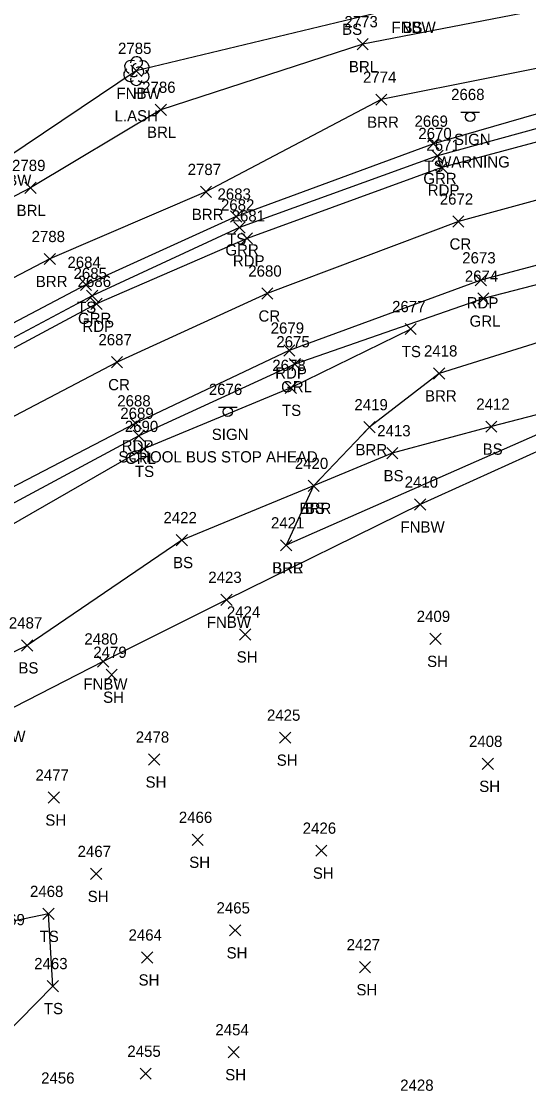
# Model space of a CAD drawing. Extents: x 1443590 to 1445966, y 578314 to 580556.
# Drawn here: x 1444460.3 to 1444550.7, y 578967.8 to 579157.3 of the extents above; entities that cross this region are included whole.
import ezdxf

# ---------------------------------------------------------------- set-up
doc = ezdxf.new("R2010")
doc.units = 0
for name, color, linetype in [('L_A', 7, 'Continuous'), ('L_C', 7, 'Continuous'), ('L_I', 7, 'Continuous'), ('L_TIC', 7, 'Continuous'), ('LABL', 7, 'Continuous'), ('LELB', 7, 'Continuous'), ('LFNC', 7, 'Continuous'), ('LTD', 7, 'Continuous'), ('P_A', 7, 'Continuous'), ('P_I', 7, 'Continuous'), ('P_TIC', 7, 'Continuous'), ('PET', 7, 'Continuous'), ('PRC', 7, 'Continuous'), ('R_A', 7, 'Continuous'), ('R_I', 7, 'Continuous'), ('R_TIC', 7, 'Continuous'), ('RGR', 7, 'Continuous'), ('S_A', 7, 'Continuous'), ('S_C', 7, 'Continuous'), ('S_I', 7, 'Continuous'), ('SSGN', 7, 'Continuous')]:
    doc.layers.add(name, color=color, linetype=linetype)

msp = doc.modelspace()

# ---------------------------------------------------------------- linework, layer by layer
at = {"layer": 'L_TIC'}
for points in [[(1444520.13, 579152.26), (1444522.13, 579154.26)], [(1444522.13, 579152.26), (1444520.13, 579154.26)], [(1444479.82, 579147.51), (1444481.82, 579149.51)], [(1444481.82, 579147.51), (1444479.82, 579149.51)], [(1444523.44, 579142.38), (1444525.44, 579144.38)], [(1444525.44, 579142.38), (1444523.44, 579144.38)], [(1444484.17, 579140.59), (1444486.17, 579142.59)], [(1444486.17, 579140.59), (1444484.17, 579142.59)], [(1444532.71, 579134.55), (1444534.71, 579136.55)], [(1444534.71, 579134.55), (1444532.71, 579136.55)], [(1444460.96, 579126.68), (1444462.96, 579128.68)], [(1444462.96, 579126.68), (1444460.96, 579128.68)], [(1444492.22, 579125.97), (1444494.22, 579127.97)], [(1444494.22, 579125.97), (1444492.22, 579127.97)], [(1444497.58, 579121.6), (1444499.58, 579123.6)], [(1444499.58, 579121.6), (1444497.58, 579123.6)], [(1444464.43, 579114.04), (1444466.43, 579116.04)], [(1444466.43, 579114.04), (1444464.43, 579116.04)], [(1444470.85, 579109.46), (1444472.85, 579111.46)], [(1444472.85, 579109.46), (1444470.85, 579111.46)], [(1444528.67, 579101.58), (1444530.67, 579103.58)], [(1444530.67, 579101.58), (1444528.67, 579103.58)], [(1444533.73, 579093.69), (1444535.73, 579095.69)], [(1444535.73, 579093.69), (1444533.73, 579095.69)], [(1444507.34, 579091.12), (1444509.34, 579093.12)], [(1444509.34, 579091.12), (1444507.34, 579093.12)], [(1444521.35, 579084.12), (1444523.35, 579086.12)], [(1444523.35, 579084.12), (1444521.35, 579086.12)], [(1444543.04, 579084.22), (1444545.04, 579086.22)], [(1444545.04, 579084.22), (1444543.04, 579086.22)], [(1444481.16, 579080.26), (1444483.16, 579082.26)], [(1444483.16, 579080.26), (1444481.16, 579082.26)], [(1444525.4, 579079.49), (1444527.4, 579081.49)], [(1444527.4, 579079.49), (1444525.4, 579081.49)], [(1444511.39, 579073.69), (1444513.39, 579075.69)], [(1444513.39, 579073.69), (1444511.39, 579075.69)], [(1444511.39, 579073.69), (1444513.39, 579075.69)], [(1444513.39, 579073.69), (1444511.39, 579075.69)], [(1444530.38, 579070.36), (1444532.38, 579072.36)], [(1444532.38, 579070.36), (1444530.38, 579072.36)], [(1444487.91, 579064.04), (1444489.91, 579066.04)], [(1444489.91, 579064.04), (1444487.91, 579066.04)], [(1444506.48, 579063.11), (1444508.48, 579065.11)], [(1444508.48, 579063.11), (1444506.48, 579065.11)], [(1444506.48, 579063.11), (1444508.48, 579065.11)], [(1444508.48, 579063.11), (1444506.48, 579065.11)], [(1444495.89, 579053.42), (1444497.89, 579055.42)], [(1444497.89, 579053.42), (1444495.89, 579055.42)], [(1444499.2, 579047.26), (1444501.2, 579049.26)], [(1444501.2, 579047.26), (1444499.2, 579049.26)], [(1444533.1, 579046.47), (1444535.1, 579048.47)], [(1444535.1, 579046.47), (1444533.1, 579048.47)], [(1444460.38, 579045.31), (1444462.38, 579047.31)], [(1444462.38, 579045.31), (1444460.38, 579047.31)], [(1444473.91, 579042.46), (1444475.91, 579044.46)], [(1444475.91, 579042.46), (1444473.91, 579044.46)], [(1444475.43, 579040.09), (1444477.43, 579042.09)], [(1444477.43, 579040.09), (1444475.43, 579042.09)], [(1444506.34, 579028.9), (1444508.34, 579030.9)], [(1444508.34, 579028.9), (1444506.34, 579030.9)], [(1444482.98, 579025), (1444484.98, 579027)], [(1444484.98, 579025), (1444482.98, 579027)], [(1444542.39, 579024.24), (1444544.39, 579026.24)], [(1444544.39, 579024.24), (1444542.39, 579026.24)], [(1444465.12, 579018.24), (1444467.12, 579020.24)], [(1444467.12, 579018.24), (1444465.12, 579020.24)], [(1444490.75, 579010.73), (1444492.75, 579012.73)], [(1444492.75, 579010.73), (1444490.75, 579012.73)], [(1444512.76, 579008.8), (1444514.76, 579010.8)], [(1444514.76, 579008.8), (1444512.76, 579010.8)], [(1444472.67, 579004.66), (1444474.67, 579006.66)], [(1444474.67, 579004.66), (1444472.67, 579006.66)], [(1444464.19, 578997.55), (1444466.19, 578999.55)], [(1444466.19, 578997.55), (1444464.19, 578999.55)], [(1444497.4, 578994.62), (1444499.4, 578996.62)], [(1444499.4, 578994.62), (1444497.4, 578996.62)], [(1444481.74, 578989.8), (1444483.74, 578991.8)], [(1444483.74, 578989.8), (1444481.74, 578991.8)], [(1444520.53, 578988.06), (1444522.53, 578990.06)], [(1444522.53, 578988.06), (1444520.53, 578990.06)], [(1444464.94, 578984.71), (1444466.94, 578986.71)], [(1444466.94, 578984.71), (1444464.94, 578986.71)], [(1444497.16, 578972.95), (1444499.16, 578974.95)], [(1444499.16, 578972.95), (1444497.16, 578974.95)], [(1444481.48, 578969.12), (1444483.48, 578971.12)], [(1444483.48, 578969.12), (1444481.48, 578971.12)]]:
    msp.add_lwpolyline(points, dxfattribs=at)
at = {"layer": 'LABL'}
for points in [[(1444712.54, 579167.85), (1444697.6, 579169.93), (1444652.08, 579178.48), (1444624.95, 579180.17), (1444611.5, 579175.57), (1444588.82, 579169.39), (1444561.97, 579161.22), (1444521.13, 579153.26), (1444485.17, 579141.59), (1444461.96, 579127.68), (1444423.87, 579107.83), (1444406.2, 579097.14), (1444395.91, 579089.33), (1444383.1, 579088.69), (1444377.98, 579081.32), (1444375.45, 579066.09), (1444387.55, 579066.41), (1444398.68, 579076.41), (1444413.49, 579086.33)], [(1444712.54, 579167.85), (1444718.35, 579164.22), (1444718.26, 579161.73), (1444696.4, 579163.57), (1444656.01, 579167.98), (1444612.17, 579160.88), (1444583.77, 579156.18), (1444564.87, 579151.47), (1444524.44, 579143.38), (1444493.22, 579126.97), (1444465.43, 579115.04), (1444435.17, 579099.27), (1444413.49, 579086.33)], [(1444694.2, 579116.07), (1444660.17, 579122.03), (1444619.71, 579118.69), (1444593.21, 579113.2), (1444563.33, 579103.61), (1444534.73, 579094.69), (1444522.35, 579085.12), (1444512.39, 579074.69), (1444507.48, 579064.11)], [(1444694.2, 579116.07), (1444661.24, 579112.36), (1444623.46, 579104.14), (1444596.63, 579097.35), (1444588.29, 579095.31), (1444555.76, 579085.36), (1444507.48, 579064.11)]]:
    msp.add_lwpolyline(points, dxfattribs=at)
at = {"layer": 'LELB'}
for points in [[(1444655.65, 579153.87), (1444655.96, 579156.44), (1444615.16, 579153.66), (1444570.72, 579146.18), (1444533.71, 579135.55), (1444498.58, 579122.6), (1444471.85, 579110.46), (1444439, 579093.18), (1444418.36, 579080.86), (1444402.03, 579073.49), (1444397.21, 579069.21), (1444392.99, 579064.18)], [(1444529.67, 579102.58), (1444508.34, 579092.12), (1444482.16, 579081.26), (1444453.29, 579064.71), (1444433.08, 579054.44), (1444417.17, 579046.55), (1444411.14, 579043.39), (1444405.77, 579042.57)], [(1444566.52, 579091.05), (1444544.04, 579085.22), (1444526.4, 579080.49), (1444512.39, 579074.69), (1444488.91, 579065.04), (1444461.38, 579046.31), (1444441.32, 579036.58), (1444429.07, 579030.89), (1444423.05, 579028.56)], [(1444453.94, 578962.61), (1444453.99, 578973.55), (1444465.94, 578985.71), (1444465.19, 578998.55), (1444446.92, 578994.78), (1444439.55, 579000.55), (1444432.64, 579022.06)]]:
    msp.add_lwpolyline(points, dxfattribs=at)
at = {"layer": 'LFNC'}
for points in [[(1444560.1, 579167.55), (1444546.27, 579164.71), (1444529.77, 579160.23), (1444480.82, 579148.51), (1444457.79, 579133.06), (1444422.53, 579110), (1444405.51, 579098.29), (1444395.54, 579091.93), (1444390.51, 579099.64), (1444385.34, 579099.67), (1444374.49, 579098.14), (1444368.47, 579095.23)], [(1444890.65, 579013.76), (1444887.91, 579035.57), (1444886.02, 579049.24), (1444887.33, 579069.98), (1444887.17, 579070.25), (1444893.55, 579088.91), (1444852.86, 579095.07), (1444811.04, 579100.21), (1444771.7, 579104.54), (1444701.16, 579115.56), (1444661.88, 579109.45), (1444623.2, 579102.04), (1444597.43, 579094.83), (1444589.4, 579093.21), (1444556.52, 579082.74), (1444531.38, 579071.36), (1444496.89, 579054.42), (1444474.91, 579043.46), (1444456.73, 579034.11), (1444432.64, 579022.06), (1444424.59, 579018.08), (1444422.86, 579017.09), (1444428.49, 579008.38), (1444434.19, 578999.12)]]:
    msp.add_lwpolyline(points, dxfattribs=at)
at = {"layer": 'LTD'}
msp.add_line((1444480.82, 579148.51), (1444480.82, 579148.51), dxfattribs=at)
msp.add_line((1444480.82, 579148.51), (1444480.82, 579148.51), dxfattribs=at)
msp.add_arc((1444480.86, 579149.95), 1.05, 335.5272, 180.9563, dxfattribs=at)
for centre, major_axis, ratio, start_param, end_param in [((1444480.02, 579149.18), (1.21, -0.51), 0.895232, 1.570796, 4.712389), ((1444481.86, 579149.1), (-1.14, -0.48), 0.949671, 1.570796, 4.712389), ((1444479.73, 579147.8), (0.58, -1.04), 0.959034, 3.141593, 6.283185), ((1444480.61, 579148.97), (-0.208, -0.792), 0.645439, 3.141593, 6.283185), ((1444481.32, 579148.35), (-0.5, 0.667), 0.989748, 3.141593, 6.283185), ((1444481.82, 579147.68), (-1.09, 0.79), 0.841452, 1.570796, 4.712389), ((1444480.82, 579147.01), (0.26, 1.06), 0.942809, 1.570796, 4.712389), ((1444480.36, 579147.76), (-0.625, -0.083), 0.423636, 0, 3.141593)]:
    msp.add_ellipse(centre, major_axis=major_axis, ratio=ratio, start_param=start_param, end_param=end_param, dxfattribs=at)
at = {"layer": 'P_TIC'}
for points in [[(1444534.21, 579130.29), (1444536.21, 579132.29)], [(1444536.21, 579130.29), (1444534.21, 579132.29)], [(1444537.16, 579120.71), (1444539.16, 579122.71)], [(1444539.16, 579120.71), (1444537.16, 579122.71)], [(1444499.53, 579117.71), (1444501.53, 579119.71)], [(1444501.53, 579117.71), (1444499.53, 579119.71)], [(1444541.16, 579110.25), (1444543.16, 579112.25)], [(1444543.16, 579110.25), (1444541.16, 579112.25)], [(1444503.14, 579107.9), (1444505.14, 579109.9)], [(1444505.14, 579107.9), (1444503.14, 579109.9)], [(1444472.73, 579106.06), (1444474.73, 579108.06)], [(1444474.73, 579106.06), (1444472.73, 579108.06)], [(1444507.06, 579097.76), (1444509.06, 579099.76)], [(1444509.06, 579097.76), (1444507.06, 579099.76)], [(1444476.38, 579095.69), (1444478.38, 579097.69)], [(1444478.38, 579095.69), (1444476.38, 579097.69)], [(1444479.73, 579084.81), (1444481.73, 579086.81)], [(1444481.73, 579084.81), (1444479.73, 579086.81)]]:
    msp.add_lwpolyline(points, dxfattribs=at)
at = {"layer": 'PET'}
for points in [[(1444572.86, 579141.4), (1444535.21, 579131.29), (1444500.53, 579118.71), (1444473.73, 579107.06), (1444441.14, 579089.65), (1444420.58, 579076.86), (1444394.66, 579061.33)], [(1444577.17, 579120.56), (1444542.16, 579111.25), (1444508.06, 579098.76), (1444480.73, 579085.81), (1444450.77, 579070.32), (1444431.1, 579059.46), (1444404.84, 579044.29), (1444399.61, 579053.05), (1444394.66, 579061.33)]]:
    msp.add_lwpolyline(points, dxfattribs=at)
at = {"layer": 'PRC'}
msp.add_lwpolyline([(1444575.01, 579131.71), (1444538.16, 579121.71), (1444504.14, 579108.9), (1444477.38, 579096.69), (1444445.79, 579080.13), (1444425.28, 579068.48), (1444399.61, 579053.05)], dxfattribs=at)
at = {"layer": 'R_TIC'}
for points in [[(1444533.43, 579132.37), (1444535.43, 579134.37)], [(1444535.43, 579132.37), (1444533.43, 579134.37)], [(1444498.2, 579119.66), (1444500.2, 579121.66)], [(1444500.2, 579119.66), (1444498.2, 579121.66)], [(1444471.94, 579107.48), (1444473.94, 579109.48)], [(1444473.94, 579107.48), (1444471.94, 579109.48)], [(1444541.61, 579106.99), (1444543.61, 579108.99)], [(1444543.61, 579106.99), (1444541.61, 579108.99)], [(1444508.05, 579095.32), (1444510.05, 579097.32)], [(1444510.05, 579095.32), (1444508.05, 579097.32)], [(1444480.27, 579082.6), (1444482.27, 579084.6)], [(1444482.27, 579082.6), (1444480.27, 579084.6)]]:
    msp.add_lwpolyline(points, dxfattribs=at)
at = {"layer": 'RGR'}
for points in [[(1444721.53, 579155.32), (1444696.74, 579155.42), (1444655.65, 579153.87), (1444615.28, 579151.28), (1444571.27, 579143.45), (1444534.43, 579133.37), (1444499.2, 579120.66), (1444472.94, 579108.48), (1444439.95, 579090.95), (1444419.6, 579078.42), (1444394.06, 579062.05)], [(1444761.39, 579118.56), (1444730.45, 579124.57), (1444695.1, 579127.47), (1444656.18, 579127.4), (1444619.28, 579124.62), (1444577.8, 579117.06), (1444542.61, 579107.99), (1444509.05, 579096.32), (1444481.27, 579083.6), (1444451.92, 579067.89), (1444431.87, 579057.62), (1444404.79, 579043.92)]]:
    msp.add_lwpolyline(points, dxfattribs=at)
at = {"layer": 'SSGN'}
for p, q in [((1444538.59, 579141.16), (1444541.93, 579141.16)), ((1444540.24, 579140.33), (1444540.24, 579140.33)), ((1444495.47, 579088.71), (1444498.8, 579088.71)), ((1444497.11, 579087.87), (1444497.11, 579087.87))]:
    msp.add_line(p, q, dxfattribs=at)
for centre in [(1444540.24, 579140.33), (1444497.11, 579087.87)]:
    msp.add_circle(centre, 0.833, dxfattribs=at)

# ---------------------------------------------------------------- texts
at = {"layer": 'L_A'}
for s, p in [('BS', (1444517.46, 579154.9)), ('FNBW', (1444526.25, 579155.23)), ('BS', (1444528.21, 579155.23)), ('BRL', (1444518.67, 579148.26)), ('FNBW', (1444477.29, 579143.51)), ('H', (1444480.25, 579143.51)), ('BRR', (1444521.92, 579138.38)), ('BRL', (1444482.72, 579136.59)), ('TS', (1444532.12, 579130.55)), ('FNBW', (1444454.26, 579128.06)), ('BRL', (1444459.5, 579122.68)), ('BRR', (1444490.7, 579121.97)), ('TS', (1444496.98, 579117.6)), ('BRR', (1444462.92, 579110.04)), ('TS', (1444470.26, 579105.46)), ('TS', (1444528.08, 579097.58)), ('BRR', (1444532.22, 579089.69)), ('TS', (1444506.75, 579087.12)), ('BRR', (1444519.84, 579080.12)), ('BS', (1444542.48, 579080.22)), ('TS', (1444480.57, 579076.26)), ('BS', (1444524.84, 579075.49)), ('BRR', (1444509.88, 579069.69)), ('BS', (1444510.83, 579069.69)), ('FNBW', (1444527.85, 579066.36)), ('BS', (1444487.36, 579060.04)), ('BRR', (1444504.97, 579059.11)), ('BRL', (1444505.02, 579059.11)), ('FNBW', (1444493.37, 579049.42)), ('SH', (1444498.68, 579043.26)), ('SH', (1444532.59, 579042.47)), ('BS', (1444459.82, 579041.31)), ('FNBW', (1444471.38, 579038.46)), ('SH', (1444474.91, 579036.09)), ('FNBW', (1444453.21, 579029.11)), ('SH', (1444505.82, 579024.9)), ('SH', (1444482.46, 579021)), ('SH', (1444541.88, 579020.24)), ('SH', (1444464.61, 579014.24)), ('SH', (1444490.24, 579006.73)), ('SH', (1444512.25, 579004.8)), ('SH', (1444472.15, 579000.66)), ('TS', (1444463.6, 578993.55)), ('SH', (1444496.89, 578990.62)), ('SH', (1444481.22, 578985.8)), ('SH', (1444520.01, 578984.06)), ('TS', (1444464.35, 578980.71)), ('SH', (1444496.65, 578968.95))]:
    msp.add_text(s, height=2, dxfattribs=at).set_placement(p)
at = {"layer": 'L_C'}
msp.add_text('L.ASH', height=2, dxfattribs=at).set_placement((1444476.94, 579139.51))
at = {"layer": 'L_I'}
for s, p in [('2773', (1444517.87, 579156.26)), ('2785', (1444477.56, 579151.51)), ('2785', (1444477.56, 579151.51)), ('2774', (1444521.18, 579146.38)), ('2786', (1444481.86, 579144.59)), ('2669', (1444530.35, 579138.55)), ('2789', (1444458.69, 579130.68)), ('2787', (1444489.96, 579129.97)), ('2683', (1444495.27, 579125.6)), ('2788', (1444462.17, 579118.04)), ('2684', (1444468.55, 579113.46)), ('2677', (1444526.36, 579105.58)), ('2418', (1444532.04, 579097.69)), ('2678', (1444505.03, 579095.12)), ('2419', (1444519.65, 579088.12)), ('2412', (1444541.35, 579088.22)), ('2690', (1444478.77, 579084.26)), ('2413', (1444523.71, 579083.49)), ('2420', (1444509.04, 579077.69)), ('2420', (1444509.04, 579077.69)), ('2410', (1444528.6, 579074.36)), ('2422', (1444485.65, 579068.04)), ('2421', (1444504.79, 579067.11)), ('2421', (1444504.79, 579067.11)), ('2423', (1444493.63, 579057.42)), ('2424', (1444496.94, 579051.26)), ('2487', (1444458.12, 579049.31)), ('2409', (1444530.75, 579050.47)), ('2480', (1444471.57, 579046.46)), ('2479', (1444473.16, 579044.09)), ('2425', (1444504.08, 579032.9)), ('2478', (1444480.72, 579029)), ('2408', (1444540.05, 579028.24)), ('2477', (1444462.86, 579022.24)), ('2466', (1444488.39, 579014.73)), ('2426', (1444510.45, 579012.8)), ('2467', (1444470.36, 579008.66)), ('2468', (1444461.88, 579001.55)), ('2465', (1444495.1, 578998.62)), ('2469', (1444455.03, 578996.53)), ('2464', (1444479.43, 578993.8)), ('2427', (1444518.27, 578992.06)), ('2463', (1444462.63, 578988.71)), ('2454', (1444494.9, 578976.95)), ('2455', (1444479.22, 578973.12)), ('2456', (1444463.87, 578968.36)), ('2428', (1444527.8, 578967.08))]:
    msp.add_text(s, height=2, dxfattribs=at).set_placement(p)
at = {"layer": 'P_A'}
for s, p in [('RDP', (1444532.7, 579126.29)), ('CR', (1444536.59, 579116.71)), ('RDP', (1444498.01, 579113.71)), ('RDP', (1444539.65, 579106.25)), ('CR', (1444502.57, 579103.9)), ('RDP', (1444471.22, 579102.06)), ('RDP', (1444505.55, 579093.76)), ('CR', (1444475.81, 579091.69)), ('RDP', (1444478.22, 579080.81))]:
    msp.add_text(s, height=2, dxfattribs=at).set_placement(p)
at = {"layer": 'P_I'}
for s, p in [('2671', (1444532.47, 579134.29)), ('2672', (1444534.85, 579124.71)), ('2681', (1444497.79, 579121.71)), ('2673', (1444538.85, 579114.25)), ('2680', (1444500.75, 579111.9)), ('2686', (1444470.37, 579110.06)), ('2679', (1444504.74, 579101.76)), ('2687', (1444474.07, 579099.69)), ('2688', (1444477.42, 579088.81))]:
    msp.add_text(s, height=2, dxfattribs=at).set_placement(p)
at = {"layer": 'R_A'}
for s, p in [('GRR', (1444531.92, 579128.37)), ('GRR', (1444496.68, 579115.66)), ('GRR', (1444470.43, 579103.48)), ('GRL', (1444540.16, 579102.99)), ('GRL', (1444506.6, 579091.32)), ('GRL', (1444478.81, 579078.6))]:
    msp.add_text(s, height=2, dxfattribs=at).set_placement(p)
at = {"layer": 'R_I'}
for s, p in [('2670', (1444531.03, 579136.37)), ('2682', (1444495.89, 579123.66)), ('2685', (1444469.64, 579111.48)), ('2674', (1444539.31, 579110.99)), ('2675', (1444505.75, 579099.32)), ('2689', (1444477.96, 579086.6))]:
    msp.add_text(s, height=2, dxfattribs=at).set_placement(p)
at = {"layer": 'S_A'}
for p in [(1444537.38, 579135.31), (1444494.25, 579082.85)]:
    msp.add_text('SIGN', height=2, dxfattribs=at).set_placement(p)
at = {"layer": 'S_C'}
for s, p in [('WARNING', (1444534.39, 579131.31)), ('SCHOOL BUS STOP AHEAD', (1444477.61, 579078.85))]:
    msp.add_text(s, height=2, dxfattribs=at).set_placement(p)
at = {"layer": 'S_I'}
for s, p in [('2668', (1444536.87, 579143.31)), ('2676', (1444493.73, 579090.85))]:
    msp.add_text(s, height=2, dxfattribs=at).set_placement(p)

doc.saveas('drawing.dxf')
